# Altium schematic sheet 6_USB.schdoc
size 309 x 223 mm; Symbol: Sheet-Symbol_A4; Device: Sheet-Symbol_A4; Company: EasyEDA.com; Drawed: EasyEDA Pro; Reviewed: EasyEDA Pro; Version: V0.1; Page Size: A4; @Project Name: CM4-Nvme-NAS-main; @Page Count: 6; @Update Date: 2023-05-06; @Create Date: 2023-05-04; @Schematic Name: RaspberryPiNVMeNAS; Part Number: JLCPCB-002; @Page No: 6; @Page Name: USB
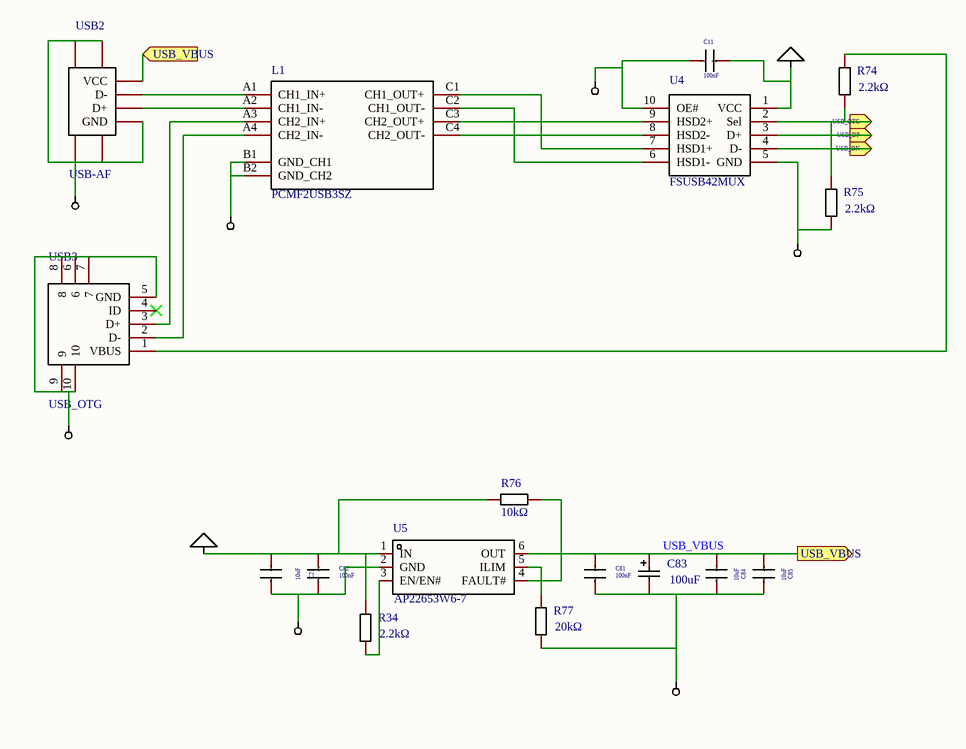
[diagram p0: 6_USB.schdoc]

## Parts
C11  100nF  [C0402]
C21  10uF  [C0805]
C81  100nF  [C0402]
C82  100nF  [C0402]
C83  100uF  [CASE-B_3528]
C84  10uF  [C0805]
C85  10uF  [C0805]
L1  PCMF2USB3SZ  [WLCSP-10_L1.6-W1.2-P0.40-BL_PCMF2USB3SZ]
R34  2.2kΩ  [R0402]
R74  2.2kΩ  [R0402]
R75  2.2kΩ  [R0402]
R76  10kΩ  [R0402]
R77  20kΩ  [R0402]
U4  FSUSB42MUX  [MSOP-10_L3.0-W3.0-P0.50-LS5.0-BL]
U5  AP22653W6-7  [SOT-23-6_L2.9-W1.6-P0.95-LS2.8-BR]
USB2  USB-AF  [USB-A-TH_USB-M-2_C26235]
USB3  USB_OTG  [MICRO-USB-SMD_47590-0001]

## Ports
USB_DN (in), USB_DP (in), USB_OTG (in), USB_VBUS (in), USB_VBUS (out)

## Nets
POWER_+3.3V: C11.2 U4.1(VCC)
POWER_+5V: C21.1 C82.2 R34.2 R76.1 U5.1(IN)
POWER_GND: C11.1 C21.2 C81.1 C82.1 C83.2 C84.2 C85.2 L1.B1(GND_CH1) L1.B2(GND_CH2) R75.1 R77.1 U4.5(GND) U4.10(OE#) U5.2(GND) USB2.4(GND) USB2.5 USB2.6 USB2.7 USB2.8 USB3.5(GND) USB3.6 USB3.7 USB3.8 USB3.9 USB3.10
USB_DN: U4.4(D-) ; port USB_DN
USB_DP: U4.3(D+) ; port USB_DP
USB_OTG: R74.1 R75.2 U4.2(Sel) ; port USB_OTG
USB_VBUS: C81.2 C83.1 C84.1 C85.1 U5.6(OUT) USB2.1(VCC) ; port USB_VBUS
NetL1_A1: L1.A1(CH1_IN+) USB2.2(D-)
NetL1_A2: L1.A2(CH1_IN-) USB2.3(D+)
NetL1_A3: L1.A3(CH2_IN+) USB3.3(D+)
NetL1_A4: L1.A4(CH2_IN-) USB3.2(D-)
NetL1_C1: L1.C1(CH1_OUT+) U4.7(HSD1+)
NetL1_C2: L1.C2(CH1_OUT-) U4.6(HSD1-)
NetL1_C3: L1.C3(CH2_OUT+) U4.9(HSD2+)
NetL1_C4: L1.C4(CH2_OUT-) U4.8(HSD2-)
NetR34_1: R34.1 U5.3(EN/EN#)
NetR74_2: R74.2 USB3.1(VBUS)
NetR76_2: R76.2 U5.4(FAULT#)
NetR77_2: R77.2 U5.5(ILIM)

Not connected (* = marked no-connect by the designer): USB3 4(ID)*

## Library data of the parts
C11 C81 C82 = CL05B104KO5NNNC: Capacitance: Tolerance:±10% Tolerance:±10% Voltage Rated: Temperature Coefficient:; Manufacturer: SAMSUNG(三星); Add into BOM: yes; Tolerance: ±10%; Origin Footprint: C_0402_1005Metric
C21 C84 C85 = CL21A106KAYNNNE_C15850: Capacitance: Tolerance:±10% Tolerance:±10% Voltage Rated: Temperature Coefficient:; Manufacturer: SAMSUNG(三星); Add into BOM: yes; Tolerance: ±10%; Origin Footprint: C_0805_2012Metric
C83 = TAJB107K006RNJ: Capacitance: Tolerance:±10% Tolerance:±10% Rated Voltage: Equivalent Series Resistance(ESR):1.7Ω@100kHz Operating Temperature:-55℃~+125℃ Operating Temperature:-55℃~+125℃; Manufacturer: Kyocera AVX; Add into BOM: yes; Tolerance: ±10%
L1 = PCMF2HDMI2BA-CZ: Manufacturer: Nexperia(安世); Add into BOM: yes
R34 R74 R75 = RC0402FR-072K2L: Type:Thick Film Resistors Resistance: Tolerance:±1% Tolerance:±1% Power(Watts): Temperature Coefficient:±100ppm/℃ Temperature Coefficient:±100ppm/℃ Overload Voltage (Max): Operating Temperature Range:-55℃~+155℃ Operating Temperature Range:-55℃~+155℃; Manufacturer: YAGEO(国巨); Add into BOM: yes; Tolerance: ±1%
R76 = 0402WGF1002TCE: Type:Thick Film Resistors Resistance: Tolerance:±1% Tolerance:±1% Power(Watts): Temperature Coefficient:±100ppm/℃ Temperature Coefficient:±100ppm/℃ Overload Voltage (Max): Operating Temperature Range:-55℃~+155℃ Operating Temperature Range:-55℃~+155℃; Manufacturer: UNI-ROYAL(厚声); Add into BOM: yes; Tolerance: ±1%
R77 = CR0402FF2002G: Type:Thick Film Resistors Resistance: Tolerance:±1% Tolerance:±1% Power(Watts): Temperature Coefficient:±200ppm/℃ Temperature Coefficient:±200ppm/℃ Overload Voltage (Max): Operating Temperature Range:-55℃~+125℃ Operating Temperature Range:-55℃~+125℃; Manufacturer: LIZ(丽智电子); Add into BOM: yes; Tolerance: ±1%
U4 = FSUSB42MUX: Manufacturer: onsemi(安森美); Add into BOM: yes
U5 = AP22653W6-7: Manufacturer: DIODES(美台); Add into BOM: yes
USB2 = USB-AF侧插铜: Connector Type:Type-A Standard:USB 2.0 Gender:Female Number of Contacts:4 Number of Ports:1; Manufacturer: 精拓金; Symbol: USB-AFSide copper; Add into BOM: yes; Connector Type: Type-A; Gender: Female; Number of Contacts: 4; Number of Ports: 1
USB3 = 475900001: Connector Type:Micro-AB Standard:- Gender:Female Number of Contacts:5 Number of Ports:1; Manufacturer: MOLEX; Symbol: 47590-0001; Add into BOM: yes; Gender: Female; Number of Contacts: 5; Number of Ports: 1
